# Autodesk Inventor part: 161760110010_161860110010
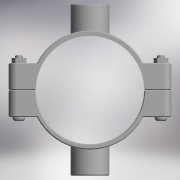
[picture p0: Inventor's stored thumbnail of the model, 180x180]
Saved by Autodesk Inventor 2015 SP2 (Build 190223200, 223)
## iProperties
Created: 2017-05
Part Number: 161760110010_161860110010
Material: Generic
Description: PLASSON DOUBLE SADDLE 110-1"
Document SubType Name: Modeling
Designer: KIM
Density: 1 g/cm^3
Appearance: Default
Author: KIM
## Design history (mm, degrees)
derived "16176.ipt"
feature "Solid1::16176.ipt"
feature "Solid2::16176.ipt"
tag "TaggingFeature1"
body "Solid1"
body "Solid2"
other parameters: "d0" = 121, "d1" = 165, "d2" = 55, "d4" = 116, "d5" = 0, "d6" = 8.25, "d7" = 165, "d8" = 0.1, "d10" = 0, "d11" = 1.1, "d20" = 1.1, "d23" = 1.1, "d36" = 13, "d37" = 10.4, "d38" = 63, "d39" = 0, "d40" = 3, "d41" = 5, "d42" = 0, "d43" = 8, "d44" = 3, "d45" = 0, "d46" = 1.1, "d52" = 30.291, "d53" = 21, "d54" = 0, "d55" = 25, "d57" = 0, "d58" = 118.8, "d60" = 0, "d62" = 13, "d63" = 10.4, "d66" = 95.2, "d67" = 174, "d68" = 39.3783, "d69" = 30.291, "d70" = 21, "d71" = 0, "d72" = 25, "d74" = 0, "d75" = 1.1, "B_" = 25, "G_" = 30.291, "A_" = 87, "L_" = 165, "L_1" = 116, "l_2" = 21
